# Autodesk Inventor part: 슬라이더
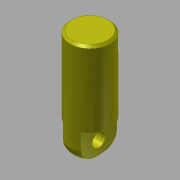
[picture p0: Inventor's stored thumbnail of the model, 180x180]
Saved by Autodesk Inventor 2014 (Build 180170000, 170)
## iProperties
Created: 2016-08
Part Number: 슬라이더
Material: 강철, 탄소
Document SubType Name: Modeling
Designer: mduedu
Density: 7.87 g/cm^3
Appearance: 노란색
Author: mduedu
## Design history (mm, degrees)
sketch "스케치1"
  geometry: C1 r 9 at (0, 0); 1 further point
  constraints: 1 centre point, 1 coincident
  dimensions: "d0" = 18 diameter of C1
extrude "돌출1" new body sketch "스케치1" distance "d1" = 47; taper "d2" = 0 deg
fillet "모깎기1" dims "d21" = 6
sketch "스케치6"
  geometry: L1 (9, 6)-(9, 47) reference; L2 (-9, 6)-(-9, 47) reference; L3 (9, 47)-(-9, 47) reference; L4 (0, 47)-(0, 0); L5 (9, 13)-(4, 13); L6 (4, 13)-(4, 0); L7 (4, 0)-(9, 0); L8 (9, 0)-(9, 13); L9 (-9, 13)-(-4, 13); L10 (-4, 13)-(-4, 0); L11 (-4, 0)-(-9, 0); L12 (-9, 0)-(-9, 13)
  constraints: 18 end point, 4 symmetric about line, 2 parallel, 2 perpendicular, 1 horizontal, 1 horizontal alignment, 1 midpoint, 1 point on line
  dimensions: "d22" = 13 distance of L7.end L5.start; "d24" = 4 distance between parallel lines of L6 L4
extrude "돌출5" cut sketch "스케치6" stored distance "d25" = 8; taper "d26" = 0 deg
sketch "스케치8"
  geometry: C1 r 3 at (6, 0); 1 further point
  constraints: 1 centre point, 1 horizontal alignment
  dimensions: "d27" = 6 diameter of C1; "d28" = 6 distance of point (0, 0) C1.centre
extrude "돌출6" cut sketch "스케치8" stored distance "d29" = 8; taper "d30" = 0 deg
chamfer "모따기2" distance "d43" = 1; stored, may be unused: second distance "d44" = 2, angle "d45" = 30 deg
node "솔리드1"
